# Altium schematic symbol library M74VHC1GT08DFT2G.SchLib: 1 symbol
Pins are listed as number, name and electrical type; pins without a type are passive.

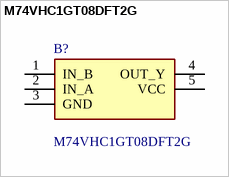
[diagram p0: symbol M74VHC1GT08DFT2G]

## M74VHC1GT08DFT2G
designator B?
Wide Operating Vcc Range; High Speed: tPD = 3.5 ns (Typ) at VCC = 5 V; Low Power Dissipation: ICC = 1A (Max) at TA = 25C; TTL-Compatible Inputs: VIL = 0.8 V; VIH = 2.0 V; CMOS-Compatible Outputs: VOH > 0.8 VCC ; VOL < 0.1 VCC @Load; Power Down Protection Provided on Inputs and Outputs; Balanced Propagation Delays; Pin and Function Compatible with Other Standard Logic Families; Chip Complexity: FETs =  100; Pb-Free Packages are Available; Manufacturer_Name: onsemi; Geometry.Height: 1.1mm
footprint SOT65P210X110-5N
pins: 1 IN_B, 2 IN_A, 3 GND, 4 OUT_Y, 5 VCC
